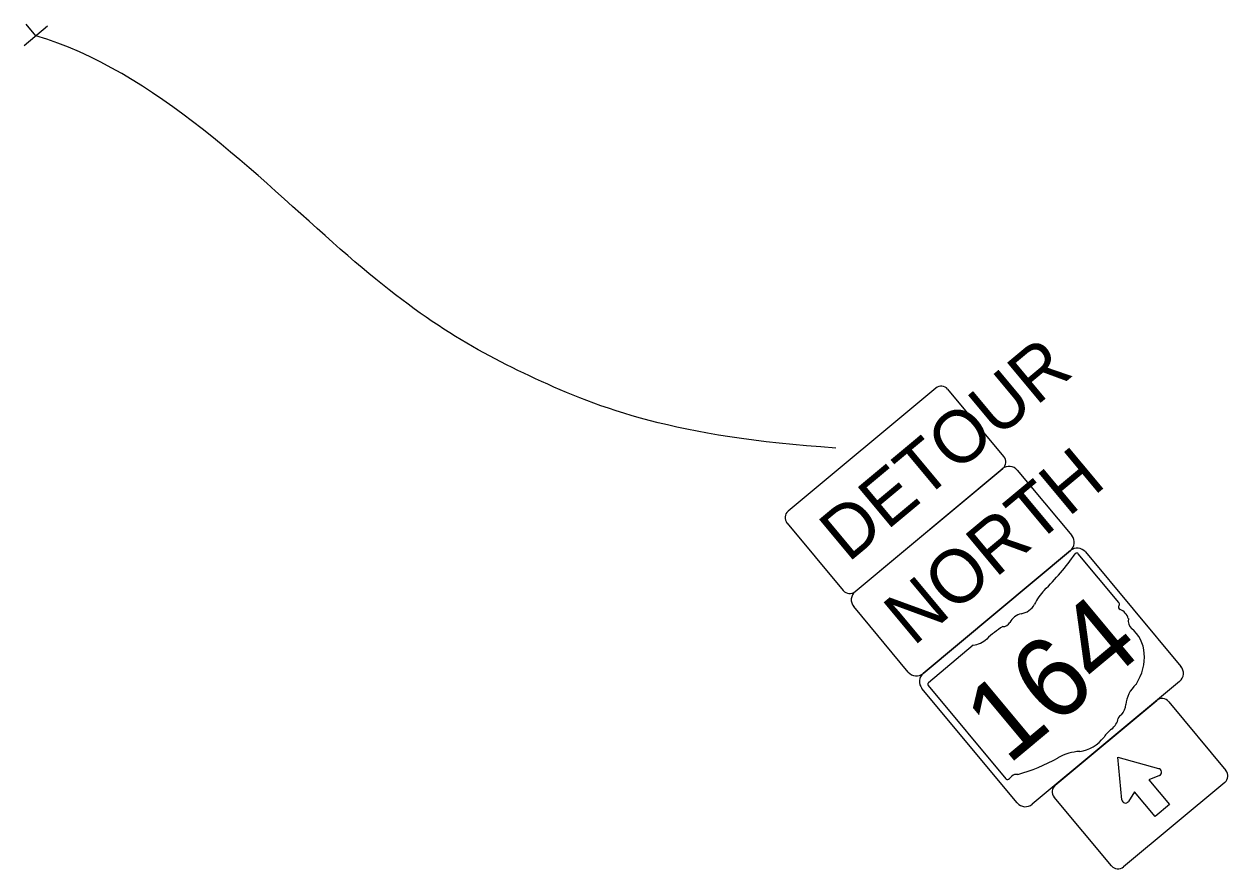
# Model space of a CAD drawing. Extents: x -202 to 1556, y 0 to 676.
# Drawn here: x -201.8 to -60.5, y 222.8 to 321.9 of the extents above; entities that cross this region are included whole.
import ezdxf

# ---------------------------------------------------------------- set-up
doc = ezdxf.new("R2010")
doc.units = 0
for name, color, linetype in [('GM_X_Minor_Lake', 7, 'Continuous'), ('GM_X_Minor_Lake_Text', 7, 'Continuous'), ('SH_Data', 7, 'Continuous')]:
    doc.layers.add(name, color=color, linetype=linetype)

msp = doc.modelspace()

# ---------------------------------------------------------------- linework, layer by layer
at = {"layer": 'GM_X_Minor_Lake'}
for p, q in [((-199.01, 321.72), (-201.77, 319.41)), ((-200.39, 320.56), (-201.54, 321.95)), ((-104.23, 255.33), (-86.95, 269.74)), ((-85.19, 269.58), (-78.79, 261.9)), ((-78.95, 260.14), (-96.23, 245.73)), ((-73.26, 254.05), (-78.03, 259.77)), ((-97.99, 245.89), (-104.39, 253.57)), ((-73.27, 254.05), (-73.26, 254.05)), ((-90.36, 249.03), (-95.63, 244.64)), ((-95.65, 244.3), (-86.54, 233.37)), ((-80.74, 232.61), (-68.83, 242.54)), ((-67.42, 242.41), (-60.7, 234.34)), ((-72.92, 230.89), (-73.38, 235.89)), ((-73.38, 235.89), (-68.62, 234.55)), ((-68.5, 233.75), (-69.74, 233.23)), ((-69.74, 233.23), (-67.34, 230.35)), ((-60.83, 232.93), (-72.73, 223.01)), ((-71.42, 231.83), (-72.15, 230.7)), ((-69.02, 228.95), (-71.42, 231.83)), ((-74.14, 223.14), (-80.87, 231.2)), ((-67.34, 230.35), (-69.02, 228.95))]:
    msp.add_line(p, q, dxfattribs=at)
for points in [[(-96.23, 245.73), (-78.95, 260.14)], [(-77.19, 259.98), (-65.98, 246.54)], [(-66.14, 244.78), (-83.43, 230.37)], [(-85.19, 230.53), (-96.39, 243.97)]]:
    msp.add_lwpolyline(points, dxfattribs=at)
for centre, radius, start, end in [((-86.15, 268.78), 1.25, 39.8151, 129.8151), ((-79.75, 261.1), 1.25, 309.8151, 39.8151), ((-78.15, 259.18), 1.25, 39.8151, 129.8151), ((-103.43, 254.37), 1.25, 129.8151, 219.8151), ((-97.03, 246.69), 1.25, 219.8151, 309.8151), ((-66.94, 245.74), 1.25, 309.8151, 39.8151), ((-95.43, 244.77), 1.25, 129.8151, 219.8151), ((-68.19, 241.77), 1, 39.8151, 129.8151), ((-68.66, 234.13), 0.417, 292.6105, 84.8246), ((-61.47, 233.7), 1, 309.8151, 39.8151), ((-80.1, 231.84), 1, 129.8151, 219.8151), ((-84.23, 231.33), 1.25, 219.8151, 309.8151), ((-72.5, 230.93), 0.417, 185.2263, 327.0197), ((-73.37, 223.78), 1, 219.8151, 309.8151)]:
    msp.add_arc(centre, radius, start, end, dxfattribs=at)
for centre, major_axis, start_param, end_param in [((-96.64, 269.05), (19.09, 15.91), 4.814394, 5.042369), ((-78.25, 259.62), (0.2, 0.167), 6.141152, 7.989035), ((-79, 252.84), (3.84, 3.2), 1.699011, 2.107814), ((-84.66, 254.39), (1.46, 1.22), 4.081561, 5.145723), ((-72.96, 253.59), (0.31, 0.259), 1.883978, 3.671073), ((-73.46, 253.85), (0.214, 0.179), 5.05454, 6.418171), ((-74.33, 251.22), (1.86, 1.55), 5.934695, 6.695948), ((-86.69, 251.9), (0.584, 0.486), 3.836095, 5.185415), ((-84.78, 251.35), (1.21, 1.01), 0.950623, 2.079405), ((-70.55, 252.25), (1.35, 1.13), 2.387724, 3.262537), ((-83.32, 244.5), (7.26, 6.05), 1.404758, 1.657858), ((-76.01, 246.47), (4.78, 3.98), 5.101752, 6.440018), ((-90.16, 251.35), (2.02, 1.69), 4.042523, 4.731795), ((-95.46, 244.5), (0.209, 0.174), 1.712693, 3.28349), ((-69.31, 242.53), (2.62, 2.18), 1.647645, 2.488434), ((-74.3, 241.78), (1.54, 1.29), 4.937069, 5.64225), ((-75.07, 240.38), (1.46, 1.22), 4.691044, 5.507374), ((-72.87, 240.42), (0.411, 0.342), 1.147584, 2.315152), ((-72.8, 237.25), (2.25, 1.87), 1.495662, 1.94098), ((-77.53, 239.72), (2.74, 2.28), 4.026481, 4.996735), ((-78.68, 231.6), (4.31, 3.6), 0.823519, 1.323587), ((-86.32, 249.13), (13.79, 11.49), 4.195997, 4.488961), ((-86.31, 233.52), (0.21, 0.175), 3.00124, 4.508301), ((-87.21, 234.66), (1.61, 1.34), 4.665946, 4.897461), ((-85.44, 233.21), (0.579, 0.483), 0.519207, 1.627899)]:
    msp.add_ellipse(centre, major_axis=major_axis, ratio=0.8, start_param=start_param, end_param=end_param, dxfattribs=at)
at = {"layer": 'GM_X_Minor_Lake_Text'}
for points in [[(-94.75, 279.22), (-112.09, 264.76)], [(-86.76, 271.18), (-93.36, 279.1)], [(-104.24, 255.33), (-86.89, 269.79)], [(-112.22, 263.38), (-105.62, 255.46)]]:
    msp.add_lwpolyline(points, dxfattribs=at)
for centre, start, end in [((-94.12, 278.47), 39.8151, 129.8151), ((-87.52, 270.55), 309.8151, 39.8151), ((-111.47, 264.01), 129.8151, 219.8151), ((-104.86, 256.09), 219.8151, 309.8151)]:
    msp.add_arc(centre, 0.982, start, end, dxfattribs=at)
at = {"layer": 'SH_Data'}
msp.add_open_spline([(-106.49, 272.18), (-125.41, 273.44), (-143.11, 280.25), (-161.4, 290.85), (-186.62, 316.61), (-200.39, 320.56)], degree=3, dxfattribs=at)

# ---------------------------------------------------------------- texts
at = {"layer": 'GM_X_Minor_Lake'}
for s, height, p in [('NORTH', 6.25, (-97.4, 248.83)), ('164', 9.375, (-86.3, 234.88))]:
    msp.add_text(s, height=height, rotation=39.8151, dxfattribs=at).set_placement(p)
at = {"layer": 'GM_X_Minor_Lake_Text'}
msp.add_text('DETOUR', height=6.138, rotation=39.8151, dxfattribs=at).set_placement((-105.04, 258.66))

doc.saveas('drawing.dxf')
